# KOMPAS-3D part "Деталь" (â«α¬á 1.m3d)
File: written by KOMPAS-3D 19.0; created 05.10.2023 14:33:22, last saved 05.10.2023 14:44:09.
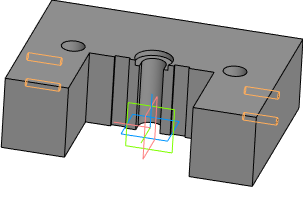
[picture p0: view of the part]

Document properties: Автор: admin; Организация: Hewlett-Packard Company; Полное имя файла: C:\Users\Petrenko-VE\Desktop\пресса 50 т\оправка один маленький подшипник\Горка_1.m3d

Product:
- Part/product: Деталь
    Масса: 25.2881

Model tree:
1. Эскиз:1
2. Элемент выдавливания:1
     Расстояние 1 = 80
3. Эскиз:2  (with: Элемент выдавливания:1)
4. Элемент выдавливания:2
     Расстояние 2 = 6
5. Эскиз:3  (with: Элемент выдавливания:1, Элемент выдавливания:2)
6. Элемент выдавливания:3
     Расстояние 2 = 80
7. Эскиз:4  (with: Элемент выдавливания:1, Элемент выдавливания:2)
8. Элемент выдавливания:4
     Расстояние 2 = 80
9. Эскиз:5  (with: Элемент выдавливания:1, Элемент выдавливания:2)
10. Элемент выдавливания:5
     Расстояние 2 = 80
11. Эскиз:6  (with: Элемент выдавливания:1, Элемент выдавливания:2, Элемент выдавливания:5)
12. Элемент выдавливания:6
     Расстояние 2 = 80
13. Эскиз:7  (with: Элемент выдавливания:1)
14. Элемент выдавливания:7
     Расстояние 2 = 50
15. Условное изображение резьбы:1  (with: Элемент выдавливания:7)  (labels: M8; cil0_24705-2004 coarse)
     Длина резьбы = 36.1573; Шаг резьбы = 1.25; Номинальный диаметр резьбы = 8
16. Подгонка:1  (with: Элемент выдавливания:7)
17. Условное изображение резьбы:2  (with: Элемент выдавливания:7)  (labels: M8; cil0_24705-2004 coarse)
     Длина резьбы = 36.1573; Шаг резьбы = 1.25; Номинальный диаметр резьбы = 8
18. Подгонка:2  (with: Элемент выдавливания:7)
19. Эскиз:8  (with: Элемент выдавливания:1)
20. Элемент выдавливания:8
     Расстояние 2 = 50
21. Условное изображение резьбы:3  (with: Элемент выдавливания:8)  (labels: M8; cil0_24705-2004 coarse)
     Длина резьбы = 36.1573; Шаг резьбы = 1.25; Номинальный диаметр резьбы = 8
22. Подгонка:3  (with: Элемент выдавливания:8)
23. Условное изображение резьбы:4  (with: Элемент выдавливания:8)  (labels: M8; cil0_24705-2004 coarse)
     Длина резьбы = 36.1573; Шаг резьбы = 1.25; Номинальный диаметр резьбы = 8
24. Подгонка:4  (with: Элемент выдавливания:8)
